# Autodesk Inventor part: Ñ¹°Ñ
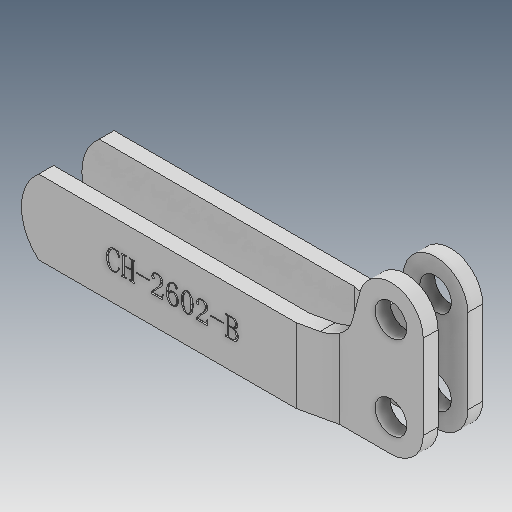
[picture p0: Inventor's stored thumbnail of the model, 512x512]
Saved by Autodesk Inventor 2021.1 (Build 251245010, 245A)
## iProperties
Created: 2020-03
Part Number: Ñ¹°Ñ
Material: Ogólny
Document SubType Name: Modeling
Designer: user
Density: 1 g/cm^3
Appearance: Domyślna
Author: user
Revision Number: ÈÎºÎ
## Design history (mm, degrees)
feature "°ü¸²1"
feature "ÇÐ³ý-À­Éì2"
node "Bryła1"
node "Bryła2"
